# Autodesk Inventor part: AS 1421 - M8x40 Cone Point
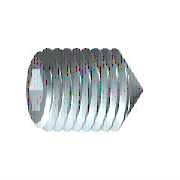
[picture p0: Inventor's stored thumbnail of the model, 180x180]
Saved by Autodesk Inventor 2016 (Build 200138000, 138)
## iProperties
IsCustomPart: 0
Created: 2015-02
Part Number: AS 1421 - M8x40 Cone Point
Material: Steel, Mild
Description: ISO metric hexagon socket set screws
Document SubType Name: Modeling
Standard: AS 1421
Designer: stank
Standards Organization: AS
Language: en-US
Size Designation: M8x40 Cone Point
Categories: <MemberInstance><Categories><Category DisplayName="Fasteners" InternalName="e4da775c-781d-43d5-af7c-5136215cf5a6" Mnemonic="FSTN"><Category DisplayName="Bolts"
Density: 7.85 g/cm^3
Appearance: Semi-Polished
Author: stank
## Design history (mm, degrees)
sketch "Sketch1"
  geometry: L1 (0, 0)-(33.667, 0); L2 (40, 2.309)-(40, 4); L3 (40, 4)-(0, 4); L4 (40, 2.309)-(35, 2.309); L5 (35, 2.309)-(33.667, 0); L6 (0, -2.4)-(0, 14.4) reference; L7 (0, 4)-(0, 0)
  constraints: 13 end point, 3 parallel, 1 collinear, 1 perpendicular, 1 point on line
  dimensions: "d0" = 5 distance of L2.start L4.end (= INTI); "d1" = 60 deg angle of L5 L1; "d2" = 8 diameter of L3 L1 (= NND); "d3" = 4.6188 diameter of L4 L1 (= 1.1547 x SW); "d5" = 40 distance from line of L2 L3.end (= NLG)
revolve "Body" sketch "Sketch1" stored, may be unused: angle "d6" = 90 deg
sketch "Sketch2"
  geometry: L1 (-1.155, 2)-(1.155, 2); L2 (1.155, 2)-(2.309, 0); L3 (2.309, 0)-(1.155, -2); L4 (1.155, -2)-(-1.155, -2); L5 (-1.155, -2)-(-2.309, 0); L6 (-2.309, 0)-(-1.155, 2); 3 further points
  constraints: 12 end point, 1 coincident, 1 horizontal, 13 other
extrude "Slot" join sketch "Sketch2" taper "d7" = 0 deg; stored distance "d21" = 10
workaxis "Work Axis1"
workplane "Work Plane1"
body "Solid1"
feature "Thread" dims "d12" = 40 (= NLG), "d13" = 0
chamfer "Chamfer1" distance "d8" = 1.73205 (computed from NND, SPD, FAWI); stored, may be unused: angle "d9" = 60 deg (= FAWI), second distance "d34" = 1.73205 (computed from NND, SPD, FAWI)
chamfer "Chamfer2" distance "d10" = 0.76681 (= -0.5 x GD1 + 0.5 x NND); stored, may be unused: angle "d11" = 60 deg (= FAWI), second distance "d35" = 0.76681 (= -0.5 x GD1 + 0.5 x NND)
other parameters: "NND" = 8 [user parameter; used in 5 equation terms], "NLG" = 40 [user parameter; used in 2 equation terms], "INTI" = 5 [user parameter; used in 1 equation term], "FAWI" = 60 deg [user parameter; used in 4 equation terms], "SW" = 4 [user parameter; used in 2 equation terms], "GD1" = 6.46637 (= THREADDIA - 1.2269 x PTC) [user parameter; used in 2 equation terms], "d4" = 0, "FAWI1" = 45 deg [user parameter], "SPD" = 2 [user parameter; used in 2 equation terms], "d36" = 0, "d37" = 0, "GUL" = 0.76681 (= 0.61345 x PTC) [user parameter], "TPU" = 8 (computed from PTC) [user parameter], "TOA" = 30 deg [user parameter], "THREADDIA" = 8 [user parameter; used in 1 equation term], "PTC" = 1.25 [user parameter; used in 4 equation terms], "GAL" = 0.76681 (= 0.61345 x PTC) [user parameter], "E0" = 4.62 (= 1.155 x SW) [user parameter]
